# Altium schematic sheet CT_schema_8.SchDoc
size 277 x 170 mm
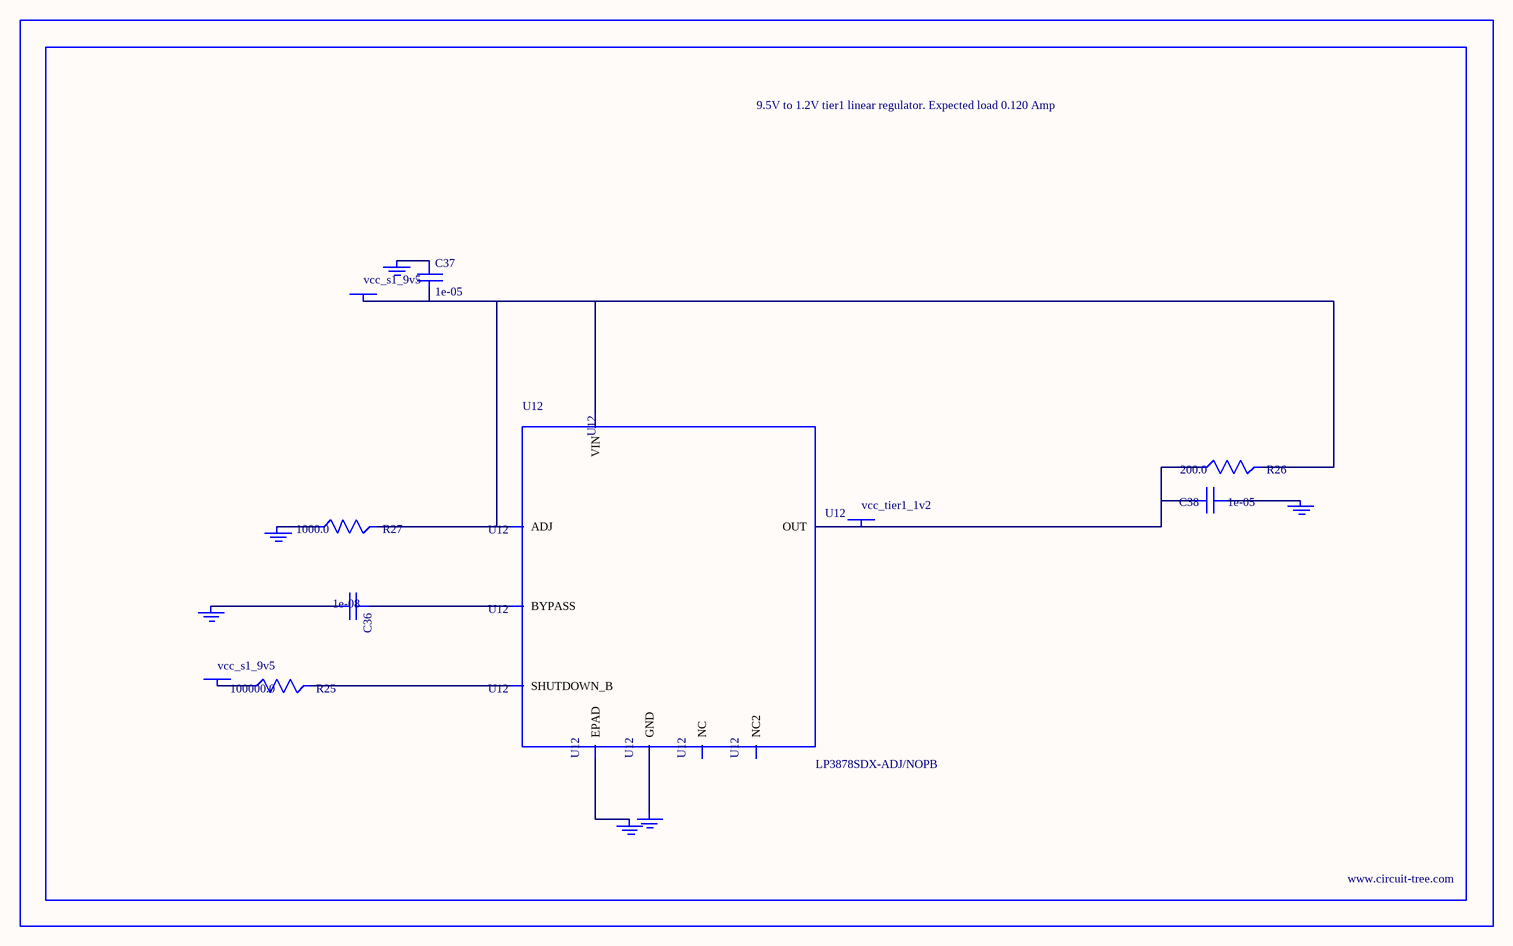
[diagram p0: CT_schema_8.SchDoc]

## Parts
BORDER7  (no value)
C36  1e-08  [C0402]
C37  1e-05  [C1206]
C38  1e-05  [C0805]
GND_INSTANCE_7_0  (no value)
GND_INSTANCE_7_1  (no value)
GND_INSTANCE_7_2  (no value)
GND_INSTANCE_7_3  (no value)
GND_INSTANCE_7_4  (no value)
GND_INSTANCE_7_5  (no value)
POWER_INSTANCE_7_0  vcc_s1_9v5
POWER_INSTANCE_7_1  vcc_s1_9v5
POWER_INSTANCE_7_2  vcc_tier1_1v2
R25  100000.0  [R0603]
R26  200.0  [R0603]
R27  1000.0  [R0603]
U12  LP3878SDX-ADJ/NOPB  [WSON-8]

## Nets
NetC36_1: C36.1 U12.1(BYPASS)
NetC36_2: C36.2 GND_INSTANCE_7_0.0(GND)
NetC37_1: C37.1 GND_INSTANCE_7_1.0(GND)
NetC37_2: C37.2 POWER_INSTANCE_7_0.0(PWR) R26.2 R27.2 U12.4(VIN) U12.6(ADJ)
NetC38_1: C38.1 GND_INSTANCE_7_2.0(GND)
NetC38_2: C38.2 POWER_INSTANCE_7_2.0(PWR) R26.1 U12.5(OUT)
NetGND_INSTANCE_7_3_0: GND_INSTANCE_7_3.0(GND) R27.1
NetGND_INSTANCE_7_4_0: GND_INSTANCE_7_4.0(GND) U12.PAD(EPAD)
NetGND_INSTANCE_7_5_0: GND_INSTANCE_7_5.0(GND) U12.3(GND)
NetPOWER_INSTANCE_7_1_0: POWER_INSTANCE_7_1.0(PWR) R25.1
NetR25_2: R25.2 U12.8(SHUTDOWN_B)

Not connected (* = marked no-connect by the designer): U12 2(NC) 7(NC2)

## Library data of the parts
BORDER7 = BORDER_PAGE7
C36 = C0402C103K3RAC
C37 = C1206C106K3RACTU
C38 = GRM219R60J106ME19D
GND_INSTANCE_7_0-GND_INSTANCE_7_5 = GND
POWER_INSTANCE_7_0-POWER_INSTANCE_7_2 = PWR
R25 = RC0603JR-07100KL
R26 = RC0603JR-07200RL
R27 = RC0603JR-071KL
